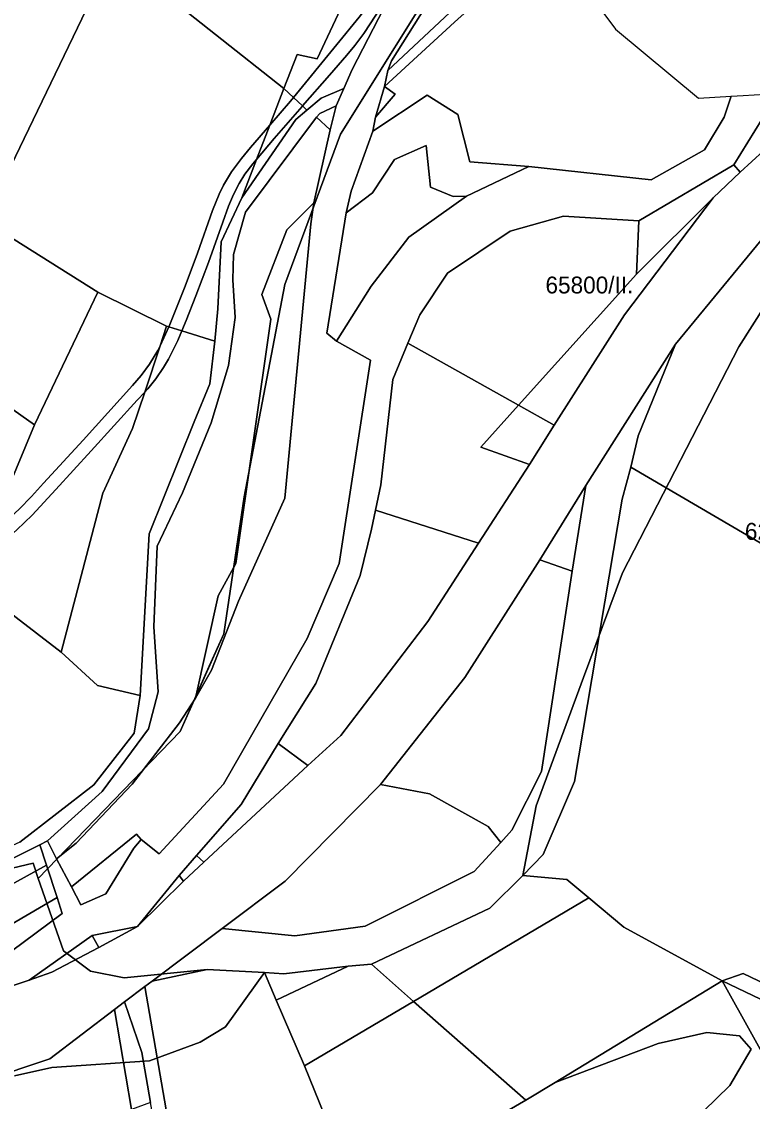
# Model space of a CAD drawing. Extents: x -521261 to -517465, y -1182764 to -1179456.
# Drawn here: x -518451.4 to -518235, y -1181892.1 to -1181572.2 of the extents above; entities that cross this region are included whole.
import ezdxf

# ---------------------------------------------------------------- set-up
doc = ezdxf.new("R2010")
doc.units = 0
for name, color, linetype in [('95610013', 7, 'Continuous'), ('95620013', 7, 'Continuous'), ('95630013', 7, 'Continuous'), ('95640013', 7, 'Continuous'), ('95660013', 7, 'Continuous')]:
    doc.layers.add(name, color=color, linetype=linetype)

msp = doc.modelspace()

# ---------------------------------------------------------------- linework, layer by layer
at = {"layer": '95610013'}
for points in [[(-518476.82, -1181511.94), (-518424.37, -1181552.23), (-518462.54, -1181631.21), (-518499.78, -1181607.82), (-518519.06, -1181596.55), (-518489.59, -1181536.73)], [(-518381.22, -1181518.57), (-518348.05, -1181547.48), (-518360.77, -1181553.84), (-518356.15, -1181566.8), (-518363.84, -1181583.23), (-518369.82, -1181581.93), (-518373.71, -1181591.99), (-518414.21, -1181559.89)], [(-518292.56, -1181544.69), (-518291.45, -1181553.08), (-518275.51, -1181574.4), (-518250.99, -1181594.82), (-518241.23, -1181594.25), (-518243.36, -1181600.52), (-518249.18, -1181610.2), (-518264.94, -1181619.06), (-518301.2, -1181615.05), (-518318.67, -1181613.69), (-518322.27, -1181599.7), (-518331.35, -1181594), (-518347.44, -1181604.6), (-518346.6, -1181600.52), (-518340.75, -1181593.69), (-518343.97, -1181591.39), (-518323.21, -1181572.31)], [(-518414.21, -1181559.89), (-518373.71, -1181591.99), (-518377.91, -1181602.87), (-518383.59, -1181609.43), (-518386.34, -1181612.73), (-518389.22, -1181616.62), (-518391.62, -1181620.62), (-518392.94, -1181623.31), (-518394.86, -1181628.09), (-518399.35, -1181640.79), (-518403.02, -1181650.57), (-518407.53, -1181661.9), (-518407.83, -1181662.59), (-518408.48, -1181662.39), (-518428.88, -1181652.36), (-518462.54, -1181631.21), (-518424.37, -1181552.23)], [(-518519.06, -1181596.55), (-518499.78, -1181607.82), (-518519.82, -1181640.58), (-518447.55, -1181691.59), (-518461.56, -1181724.91), (-518464.37, -1181727.16), (-518465.48, -1181727.97), (-518521.74, -1181659.28), (-518523.32, -1181646.7), (-518529.15, -1181635.61), (-518540.13, -1181623.13), (-518535.82, -1181617.93), (-518521.74, -1181594.76)], [(-518231.23, -1181593.65), (-518226.03, -1181593.35), (-518228.23, -1181607.32), (-518238.63, -1181616.76), (-518240.53, -1181614.63), (-518232.17, -1181601.16)], [(-518364.04, -1181600.44), (-518360.05, -1181604.26), (-518364.91, -1181625.87), (-518372.83, -1181633.83), (-518380.25, -1181653.03), (-518377.62, -1181660.36), (-518387.93, -1181732.71), (-518393.16, -1181742.24), (-518399.93, -1181772.58), (-518404.68, -1181779.92), (-518418.7, -1181798.11), (-518435.27, -1181815.58), (-518441.04, -1181820.23), (-518443.71, -1181814.88), (-518427.58, -1181800.22), (-518413.83, -1181781.65), (-518410.94, -1181770.72), (-518412.23, -1181751.5), (-518411.22, -1181727.56), (-518403.75, -1181711.81), (-518395.27, -1181691.01), (-518390.12, -1181674.09), (-518388.2, -1181659.86), (-518388.81, -1181648.68), (-518388.69, -1181641.14), (-518385.08, -1181628.59)], [(-518210.43, -1181608.65), (-518201.08, -1181598.66), (-518162.04, -1181630.84), (-518143.65, -1181649.33), (-518166.09, -1181691.8), (-518181.28, -1181714.22), (-518201.57, -1181744.52), (-518211.74, -1181738.87), (-518271.03, -1181704.12), (-518268.81, -1181694.86), (-518257.78, -1181667.72), (-518223.62, -1181626.24)], [(-518462.54, -1181631.21), (-518428.88, -1181652.36), (-518447.55, -1181691.59), (-518519.82, -1181640.58), (-518499.78, -1181607.82)], [(-518331.62, -1181608.89), (-518330.32, -1181621.26), (-518323.64, -1181623.98), (-518319.67, -1181623.86), (-518336.69, -1181636.07), (-518347.92, -1181650.56), (-518358.17, -1181666.8), (-518361, -1181664.46), (-518355.26, -1181628.81), (-518347.5, -1181622.93), (-518340.99, -1181613.05)], [(-518382.91, -1181614.3), (-518381.83, -1181613.01), (-518386.22, -1181624.34), (-518392.34, -1181637.45), (-518393.34, -1181657.24), (-518394.18, -1181666.81), (-518403.95, -1181663.79), (-518402.66, -1181660.73), (-518399.81, -1181653.43), (-518396.07, -1181643.56), (-518391.82, -1181631.62), (-518390.11, -1181626.85), (-518388.64, -1181623.36), (-518386.98, -1181620.16), (-518385.28, -1181617.37)], [(-518268.65, -1181631.19), (-518269.27, -1181646.99), (-518304.23, -1181685.78), (-518337.01, -1181667.42), (-518333.51, -1181659), (-518325.31, -1181646.7), (-518306.77, -1181634.23), (-518290.9, -1181629.82)], [(-518408.48, -1181662.39), (-518410.41, -1181668.2), (-518411.08, -1181669.58), (-518413.54, -1181673.62), (-518416, -1181676.99), (-518418.57, -1181679.95), (-518433.23, -1181696.12), (-518444.89, -1181708.88), (-518448.47, -1181712.84), (-518452.15, -1181716.64), (-518455.79, -1181720.01), (-518459.63, -1181723.36), (-518461.56, -1181724.91), (-518447.55, -1181691.59), (-518428.88, -1181652.36)], [(-518407.83, -1181662.59), (-518409.26, -1181665.86), (-518410.41, -1181668.2), (-518408.48, -1181662.39)], [(-518405.17, -1181666.68), (-518403.95, -1181663.79), (-518394.18, -1181666.81), (-518395.65, -1181679.45), (-518400.32, -1181690.69), (-518413.6, -1181723.96), (-518416.35, -1181771.83), (-518428.93, -1181768.84), (-518439.74, -1181758.97), (-518427.4, -1181711.89), (-518418.53, -1181692.71), (-518414.95, -1181681.93), (-518414.04, -1181680.93), (-518411.64, -1181677.96), (-518409.37, -1181674.6), (-518407.95, -1181672.17), (-518406.68, -1181669.78)], [(-518337.01, -1181667.42), (-518304.23, -1181685.78), (-518315.44, -1181698.22), (-518301.03, -1181703.4), (-518316.1, -1181726.67), (-518346.59, -1181716.86), (-518345, -1181709.41), (-518341.51, -1181678.22)], [(-518417.17, -1181684.34), (-518414.95, -1181681.93), (-518418.53, -1181692.71), (-518427.4, -1181711.89), (-518439.74, -1181758.97), (-518460.42, -1181743.1), (-518462.64, -1181741.12), (-518466.51, -1181737.53), (-518464.59, -1181732.37), (-518461.48, -1181730.07), (-518458.77, -1181727.94), (-518456.47, -1181725.99), (-518452.81, -1181722.77), (-518448.24, -1181718.36), (-518441.26, -1181710.8), (-518430.81, -1181699.37)], [(-518273.51, -1181713.67), (-518271.03, -1181704.12), (-518211.74, -1181738.87), (-518201.57, -1181744.52), (-518174.5, -1181758.25), (-518185.6, -1181810.01), (-518196.73, -1181867.61), (-518217.29, -1181863.99), (-518237.7, -1181854.2), (-518243.96, -1181856.31), (-518273.09, -1181840.42), (-518283.47, -1181831.75), (-518289.97, -1181826.31), (-518302.96, -1181825.14), (-518296.94, -1181818.88), (-518287.7, -1181797.29)], [(-518346.59, -1181716.86), (-518316.1, -1181726.67), (-518331.13, -1181749.88), (-518356.9, -1181783.65), (-518366.69, -1181792.51), (-518375.39, -1181786.06), (-518364.24, -1181768.26), (-518351.11, -1181736.23), (-518347.8, -1181722.52)], [(-518460.42, -1181743.1), (-518439.74, -1181758.97), (-518428.93, -1181768.84), (-518416.35, -1181771.83), (-518418.1, -1181782.97), (-518430.01, -1181798.28), (-518451.98, -1181815.29), (-518465.35, -1181821.3), (-518479.21, -1181819.93), (-518486.56, -1181817.64), (-518501.45, -1181807.02), (-518529.59, -1181794.49), (-518566.25, -1181771.18), (-518553.91, -1181776.63), (-518531.62, -1181780.05), (-518502.35, -1181773.42), (-518481.38, -1181762.2)], [(-518404.75, -1181825.16), (-518403.42, -1181826.84), (-518417.05, -1181840.21)], [(-518417.05, -1181840.21), (-518428.59, -1181846.46), (-518430.51, -1181842.88)], [(-518396.5, -1181852.96), (-518379.46, -1181853.84), (-518376.06, -1181862.1), (-518367.68, -1181881.56), (-518357.49, -1181906.63), (-518350.22, -1181919.64), (-518342.33, -1181934.69), (-518357.25, -1181947.67), (-518394.95, -1181973.55), (-518397.34, -1181959.64), (-518414.92, -1181857.99), (-518412.79, -1181856.47)], [(-518373.71, -1181854.29), (-518354.74, -1181851.96), (-518376.06, -1181862.1), (-518379.46, -1181853.84)], [(-518354.74, -1181851.96), (-518347.83, -1181851.39), (-518335.33, -1181862.43), (-518367.68, -1181881.56), (-518376.06, -1181862.1)], [(-518367.68, -1181881.56), (-518335.33, -1181862.43), (-518302.11, -1181891.7), (-518350.22, -1181919.64), (-518357.49, -1181906.63)], [(-518443.06, -1181879.44), (-518423.93, -1181864.88), (-518418.91, -1181894.43), (-518563.19, -1181948.17), (-518569.57, -1181929.4), (-518533.23, -1181906.38), (-518501.17, -1181898.93)], [(-518238.76, -1181872.67), (-518235.39, -1181876.59), (-518241.66, -1181887.31), (-518292.42, -1181936.84), (-518324.52, -1181960.18), (-518326.35, -1181957.27), (-518342.33, -1181934.69), (-518350.22, -1181919.64), (-518302.11, -1181891.7), (-518293.39, -1181886.48), (-518262.89, -1181874.89), (-518248.46, -1181871.63)]]:
    msp.add_lwpolyline(points, close=True, dxfattribs=at)
msp.add_lwpolyline([(-518463.58, -1181824.77), (-518446.06, -1181816.02), (-518444.06, -1181822.06), (-518462.21, -1181832.05)], dxfattribs=at)
at = {"layer": '95620013'}
for points in [[(-518174.5, -1181758.25), (-518176.04, -1181791.27), (-518184.18, -1181816.88), (-518186.5, -1181837.96), (-518187.07, -1181860.77), (-518193.46, -1181875.24), (-518206.25, -1181872.88), (-518216.74, -1181869.34), (-518243.96, -1181856.31), (-518237.7, -1181854.2), (-518217.29, -1181863.99), (-518196.73, -1181867.61), (-518185.6, -1181810.01)], [(-518302.96, -1181825.14), (-518289.97, -1181826.31), (-518283.47, -1181831.75), (-518335.33, -1181862.43), (-518347.83, -1181851.39), (-518312.78, -1181834.79)], [(-518283.47, -1181831.75), (-518273.09, -1181840.42), (-518243.96, -1181856.31), (-518293.39, -1181886.48), (-518302.11, -1181891.7), (-518335.33, -1181862.43)], [(-518243.96, -1181856.31), (-518216.74, -1181869.34), (-518206.25, -1181872.88), (-518193.46, -1181875.24), (-518210.07, -1181898.25), (-518234.59, -1181915.51), (-518260.74, -1181923.8), (-518297.47, -1181944.62), (-518324.52, -1181960.18), (-518292.42, -1181936.84), (-518241.77, -1181903.92), (-518224.92, -1181890.6)], [(-518238.76, -1181872.67), (-518248.46, -1181871.63), (-518262.89, -1181874.89), (-518293.39, -1181886.48), (-518243.96, -1181856.31), (-518224.92, -1181890.6), (-518241.77, -1181903.92), (-518292.42, -1181936.84), (-518241.66, -1181887.31), (-518235.39, -1181876.59)]]:
    msp.add_lwpolyline(points, close=True, dxfattribs=at)
at = {"layer": '95630013'}
for points in [[(-518292.99, -1181541.03), (-518292.56, -1181544.69), (-518323.21, -1181572.31), (-518343.97, -1181591.39), (-518343, -1181586.61), (-518304.74, -1181550.83)], [(-518284.29, -1181709.64), (-518288.33, -1181734.98), (-518297.97, -1181731.65)], [(-518297.97, -1181731.65), (-518288.33, -1181734.98), (-518297.49, -1181794.35), (-518306.21, -1181811.72), (-518309.53, -1181815.34), (-518313.24, -1181810.57), (-518330.63, -1181800.91), (-518345.1, -1181798.17), (-518320.12, -1181766.51)], [(-518345.1, -1181798.17), (-518330.63, -1181800.91), (-518313.24, -1181810.57), (-518309.53, -1181815.34), (-518317.42, -1181823.95), (-518349.68, -1181840.18), (-518370.51, -1181842.96), (-518392.04, -1181840.87), (-518373.39, -1181826.78)]]:
    msp.add_lwpolyline(points, close=True, dxfattribs=at)
for points in [[(-518451.98, -1181815.29), (-518430.01, -1181798.28), (-518418.1, -1181782.97), (-518416.35, -1181771.83), (-518413.6, -1181723.96), (-518400.32, -1181690.69), (-518395.65, -1181679.45), (-518394.18, -1181666.81), (-518393.34, -1181657.24), (-518392.34, -1181637.45), (-518386.22, -1181624.34), (-518370.22, -1181601.17), (-518366.91, -1181598.39), (-518362.67, -1181594.83), (-518355.96, -1181592.03), (-518358.22, -1181597.08), (-518363.05, -1181599.36), (-518364.04, -1181600.44), (-518385.08, -1181628.59), (-518388.69, -1181641.14), (-518388.81, -1181648.68), (-518388.2, -1181659.86), (-518390.12, -1181674.09), (-518395.27, -1181691.01), (-518403.75, -1181711.81), (-518411.22, -1181727.56), (-518412.23, -1181751.5), (-518410.94, -1181770.72), (-518413.83, -1181781.65), (-518427.58, -1181800.22), (-518443.71, -1181814.88), (-518446.06, -1181816.02), (-518463.58, -1181824.77)], [(-518462.19, -1181853.28), (-518439.36, -1181836.36), (-518440.9, -1181831.61), (-518444.06, -1181822.06), (-518446.06, -1181816.02), (-518443.71, -1181814.88), (-518441.04, -1181820.23), (-518436.68, -1181828.52), (-518433.85, -1181833.87), (-518426.44, -1181830.61), (-518418.2, -1181817.08), (-518415.97, -1181814.43), (-518410.71, -1181818.75), (-518391.63, -1181798.11), (-518366.86, -1181754.89), (-518357.33, -1181732.66), (-518348.13, -1181672.51), (-518358.17, -1181666.8), (-518347.92, -1181650.56), (-518336.69, -1181636.07), (-518319.67, -1181623.86), (-518301.2, -1181615.05), (-518264.94, -1181619.06), (-518249.18, -1181610.2), (-518243.36, -1181600.52), (-518241.23, -1181594.25), (-518237.69, -1181594.04), (-518231.23, -1181593.65)], [(-518232.17, -1181601.16), (-518240.53, -1181614.63), (-518268.65, -1181631.19), (-518290.9, -1181629.82), (-518306.77, -1181634.23), (-518325.31, -1181646.7), (-518333.51, -1181659), (-518337.01, -1181667.42), (-518341.51, -1181678.22), (-518345, -1181709.41), (-518346.59, -1181716.86), (-518347.8, -1181722.52), (-518351.11, -1181736.23), (-518364.24, -1181768.26), (-518375.39, -1181786.06), (-518386.42, -1181804.08), (-518399.59, -1181819.23), (-518404.75, -1181825.16), (-518417.05, -1181840.21), (-518430.51, -1181842.88), (-518449.2, -1181856.15), (-518511.46, -1181876.67)]]:
    msp.add_lwpolyline(points, dxfattribs=at)
at = {"layer": '95640013'}
for points in [[(-518292.92, -1181519.25), (-518288.8, -1181522.19), (-518294.6, -1181527.65), (-518292.99, -1181541.03), (-518304.74, -1181550.83), (-518343, -1181586.61), (-518341.85, -1181583.76), (-518330.14, -1181565.02)], [(-518348.05, -1181547.48), (-518340.67, -1181554.63), (-518345.13, -1181561.85), (-518348.85, -1181567.48), (-518351.43, -1181570.85), (-518358.03, -1181578.9), (-518370.88, -1181594.65), (-518373.71, -1181591.99), (-518369.82, -1181581.93), (-518363.84, -1181583.23), (-518356.15, -1181566.8), (-518360.77, -1181553.84)], [(-518340.67, -1181554.63), (-518338.07, -1181557.14), (-518338.36, -1181557.58), (-518346.55, -1181570.23), (-518350.1, -1181575.69), (-518352.7, -1181579.27), (-518355.05, -1181582.12), (-518360.25, -1181588.07), (-518368.24, -1181597.13), (-518370.88, -1181594.65), (-518358.03, -1181578.9), (-518351.43, -1181570.85), (-518348.85, -1181567.48), (-518345.13, -1181561.85)], [(-518338.36, -1181557.58), (-518338.07, -1181557.14), (-518337.29, -1181557.9), (-518342.54, -1181565.05), (-518353.55, -1181586.4), (-518355.96, -1181592.03), (-518362.67, -1181594.83), (-518366.91, -1181598.39), (-518368.24, -1181597.13), (-518360.25, -1181588.07), (-518355.05, -1181582.12), (-518352.7, -1181579.27), (-518350.1, -1181575.69), (-518346.55, -1181570.23)], [(-518373.71, -1181591.99), (-518370.88, -1181594.65), (-518371.79, -1181595.78), (-518377.91, -1181602.87)], [(-518343.97, -1181591.39), (-518340.75, -1181593.69), (-518346.6, -1181600.52)], [(-518370.88, -1181594.65), (-518368.24, -1181597.13), (-518368.36, -1181597.27), (-518376.62, -1181606.83), (-518381.83, -1181613.01), (-518377.91, -1181602.87), (-518371.79, -1181595.78)], [(-518322.27, -1181599.7), (-518318.67, -1181613.69), (-518301.2, -1181615.05), (-518319.67, -1181623.86), (-518323.64, -1181623.98), (-518330.32, -1181621.26), (-518331.62, -1181608.89), (-518340.99, -1181613.05), (-518347.5, -1181622.93), (-518355.26, -1181628.81), (-518353.86, -1181622.4), (-518347.44, -1181604.6), (-518331.35, -1181594)], [(-518368.36, -1181597.27), (-518368.24, -1181597.13), (-518366.91, -1181598.39), (-518370.22, -1181601.17), (-518386.22, -1181624.34), (-518381.83, -1181613.01), (-518376.62, -1181606.83)], [(-518358.22, -1181597.08), (-518360.05, -1181604.26), (-518364.04, -1181600.44), (-518363.05, -1181599.36)], [(-518377.91, -1181602.87), (-518381.83, -1181613.01), (-518382.91, -1181614.3), (-518385.28, -1181617.37), (-518386.98, -1181620.16), (-518388.64, -1181623.36), (-518390.11, -1181626.85), (-518391.82, -1181631.62), (-518396.07, -1181643.56), (-518399.81, -1181653.43), (-518402.66, -1181660.73), (-518403.95, -1181663.79), (-518407.83, -1181662.59), (-518407.53, -1181661.9), (-518403.02, -1181650.57), (-518399.35, -1181640.79), (-518394.86, -1181628.09), (-518392.94, -1181623.31), (-518391.62, -1181620.62), (-518389.22, -1181616.62), (-518386.34, -1181612.73), (-518383.59, -1181609.43)], [(-518240.53, -1181614.63), (-518238.63, -1181616.76), (-518246.56, -1181624.36), (-518269.27, -1181646.99), (-518268.65, -1181631.19)], [(-518364.91, -1181625.87), (-518365.73, -1181632.04), (-518373.41, -1181713.36), (-518387.15, -1181743.87), (-518395.15, -1181764.35), (-518399.93, -1181772.58), (-518393.16, -1181742.24), (-518387.93, -1181732.71), (-518377.62, -1181660.36), (-518380.25, -1181653.03), (-518372.83, -1181633.83)], [(-518269.27, -1181646.99), (-518246.56, -1181624.36), (-518272.91, -1181659.04), (-518293.66, -1181691.71), (-518304.23, -1181685.78)], [(-518407.83, -1181662.59), (-518403.95, -1181663.79), (-518405.17, -1181666.68), (-518406.68, -1181669.78), (-518407.95, -1181672.17), (-518409.37, -1181674.6), (-518411.64, -1181677.96), (-518414.04, -1181680.93), (-518414.95, -1181681.93), (-518410.41, -1181668.2), (-518409.26, -1181665.86)], [(-518410.41, -1181668.2), (-518414.95, -1181681.93), (-518417.17, -1181684.34), (-518430.81, -1181699.37), (-518441.26, -1181710.8), (-518448.24, -1181718.36), (-518452.81, -1181722.77), (-518456.47, -1181725.99), (-518458.77, -1181727.94), (-518461.48, -1181730.07), (-518464.59, -1181732.37), (-518463.74, -1181730.1), (-518461.56, -1181724.91), (-518459.63, -1181723.36), (-518455.79, -1181720.01), (-518452.15, -1181716.64), (-518448.47, -1181712.84), (-518444.89, -1181708.88), (-518433.23, -1181696.12), (-518418.57, -1181679.95), (-518416, -1181676.99), (-518413.54, -1181673.62), (-518411.08, -1181669.58)], [(-518268.81, -1181694.86), (-518271.03, -1181704.12), (-518273.51, -1181713.67), (-518287.7, -1181797.29), (-518296.94, -1181818.88), (-518302.96, -1181825.14), (-518312.78, -1181834.79), (-518347.83, -1181851.39), (-518354.74, -1181851.96), (-518373.71, -1181854.29), (-518379.46, -1181853.84), (-518396.5, -1181852.96), (-518412.79, -1181856.47), (-518392.04, -1181840.87), (-518370.51, -1181842.96), (-518349.68, -1181840.18), (-518317.42, -1181823.95), (-518309.53, -1181815.34), (-518306.21, -1181811.72), (-518297.49, -1181794.35), (-518288.33, -1181734.98), (-518284.29, -1181709.64), (-518257.78, -1181667.72)], [(-518304.23, -1181685.78), (-518293.66, -1181691.71), (-518298.38, -1181699.15), (-518301.03, -1181703.4), (-518315.44, -1181698.22)], [(-518375.39, -1181786.06), (-518366.69, -1181792.51), (-518397.42, -1181821.23), (-518399.59, -1181819.23), (-518386.42, -1181804.08)], [(-518415.97, -1181814.43), (-518418.2, -1181817.08), (-518426.44, -1181830.61), (-518433.85, -1181833.87), (-518436.68, -1181828.52), (-518417.35, -1181812.86)], [(-518397.42, -1181821.23), (-518403.42, -1181826.84), (-518404.75, -1181825.16), (-518399.59, -1181819.23)], [(-518440.9, -1181831.61), (-518439.36, -1181836.36), (-518462.19, -1181853.28), (-518493.06, -1181867.9), (-518531.13, -1181867.61), (-518550.76, -1181876.48), (-518584.29, -1181866.38), (-518588.11, -1181867.31), (-518597.74, -1181856.58), (-518562.08, -1181864.17), (-518526.41, -1181862.85), (-518492.11, -1181855.83), (-518458.32, -1181841.87)], [(-518430.51, -1181842.88), (-518428.59, -1181846.46), (-518442.42, -1181853.8), (-518449.2, -1181856.15)], [(-518420.92, -1181862.58), (-518414.92, -1181857.99), (-518397.34, -1181959.64), (-518406.88, -1181927.15), (-518413.21, -1181892.42), (-518415.81, -1181877.57)], [(-518423.93, -1181864.88), (-518420.92, -1181862.58), (-518415.81, -1181877.57), (-518413.21, -1181892.42), (-518418.91, -1181894.43)]]:
    msp.add_lwpolyline(points, close=True, dxfattribs=at)
for points in [[(-518330.14, -1181565.02), (-518341.85, -1181583.76), (-518343, -1181586.61), (-518343.97, -1181591.39), (-518346.6, -1181600.52), (-518347.44, -1181604.6), (-518353.86, -1181622.4), (-518355.26, -1181628.81), (-518361, -1181664.46), (-518358.17, -1181666.8), (-518348.13, -1181672.51), (-518357.33, -1181732.66), (-518366.86, -1181754.89), (-518391.63, -1181798.11), (-518410.71, -1181818.75), (-518415.97, -1181814.43), (-518417.35, -1181812.86), (-518436.68, -1181828.52), (-518441.04, -1181820.23), (-518435.27, -1181815.58), (-518418.7, -1181798.11), (-518404.68, -1181779.92), (-518399.93, -1181772.58), (-518395.15, -1181764.35), (-518387.15, -1181743.87), (-518373.41, -1181713.36), (-518365.73, -1181632.04), (-518364.91, -1181625.87), (-518360.05, -1181604.26), (-518358.22, -1181597.08), (-518355.96, -1181592.03), (-518353.55, -1181586.4), (-518342.54, -1181565.05)], [(-518511.46, -1181876.67), (-518449.2, -1181856.15), (-518442.42, -1181853.8), (-518428.59, -1181846.46), (-518417.05, -1181840.21), (-518403.42, -1181826.84), (-518397.42, -1181821.23), (-518366.69, -1181792.51), (-518356.9, -1181783.65), (-518331.13, -1181749.88), (-518316.1, -1181726.67), (-518301.03, -1181703.4), (-518298.38, -1181699.15), (-518293.66, -1181691.71), (-518272.91, -1181659.04), (-518246.56, -1181624.36), (-518238.63, -1181616.76), (-518228.23, -1181607.32)], [(-518223.62, -1181626.24), (-518257.78, -1181667.72), (-518284.29, -1181709.64), (-518297.97, -1181731.65), (-518320.12, -1181766.51), (-518345.1, -1181798.17), (-518373.39, -1181826.78), (-518392.04, -1181840.87), (-518412.79, -1181856.47), (-518414.92, -1181857.99), (-518420.92, -1181862.58), (-518423.93, -1181864.88), (-518443.06, -1181879.44), (-518501.17, -1181898.93), (-518533.23, -1181906.38), (-518560.65, -1181908.71), (-518594.09, -1181908.98), (-518616.77, -1181907.64), (-518653.59, -1181905.09), (-518704.59, -1181895.96), (-518740.3, -1181896.33), (-518841.96, -1181963.21)], [(-518462.21, -1181832.05), (-518444.06, -1181822.06), (-518440.9, -1181831.61), (-518458.32, -1181841.87)]]:
    msp.add_lwpolyline(points, dxfattribs=at)
at = {"layer": '95660013'}
for points in [[(-518292, -1181501.5), (-518357, -1181605.5), (-518373.5, -1181650), (-518385.5, -1181713), (-518391.5, -1181753.5), (-518404.5, -1181782.5), (-518446.5, -1181826), (-518448, -1181821.5), (-518463, -1181825), (-518477, -1181825), (-518506, -1181816), (-518572, -1181787), (-518554.5, -1181761), (-518541, -1181732.5), (-518535.5, -1181702.5), (-518541, -1181680), (-518568, -1181628), (-518591, -1181563)], [(-518222.5, -1181642.5), (-518239, -1181668.5), (-518273.5, -1181735.5), (-518285, -1181766.5), (-518299, -1181804.5), (-518302.96, -1181825.14), (-518312.78, -1181834.79), (-518347.83, -1181851.39), (-518354.74, -1181851.96), (-518373.71, -1181854.29), (-518379.46, -1181853.84), (-518396.5, -1181852.96), (-518421, -1181855.5), (-518431, -1181853.5), (-518439, -1181847.5), (-518446.5, -1181826), (-518404.5, -1181782.5), (-518395.82, -1181763.13), (-518391.5, -1181753.5), (-518385.5, -1181713), (-518373.5, -1181650), (-518357, -1181605.5), (-518292, -1181501.5)], [(-518232.93, -1181508.15), (-518243.76, -1181510.04), (-518252.51, -1181510.92), (-518279.66, -1181513.62), (-518288.8, -1181522.19), (-518294.6, -1181527.65), (-518292.99, -1181541.03), (-518292.56, -1181544.69), (-518291.45, -1181553.08), (-518275.51, -1181574.4), (-518250.99, -1181594.82), (-518241.23, -1181594.25), (-518237.69, -1181594.04), (-518231.23, -1181593.65)], [(-518217.29, -1181863.99), (-518237.7, -1181854.2), (-518243.96, -1181856.31), (-518273.09, -1181840.42), (-518283.47, -1181831.75), (-518289.97, -1181826.31), (-518302.96, -1181825.14), (-518299, -1181804.5), (-518285, -1181766.5), (-518273.5, -1181735.5), (-518239, -1181668.5), (-518222.5, -1181642.5)], [(-518463, -1181825), (-518448, -1181821.5), (-518446.5, -1181826), (-518439, -1181847.5), (-518431, -1181853.5), (-518421, -1181855.5), (-518396.5, -1181852.96), (-518379.46, -1181853.84), (-518391, -1181870), (-518398.5, -1181874.5), (-518413.5, -1181880), (-518442.5, -1181882), (-518453.5, -1181884.5)], [(-518292.42, -1181936.84), (-518241.66, -1181887.31), (-518235.39, -1181876.59), (-518238.76, -1181872.67), (-518248.46, -1181871.63), (-518262.89, -1181874.89), (-518293.39, -1181886.48), (-518302.11, -1181891.7), (-518335.33, -1181862.43), (-518347.83, -1181851.39), (-518312.78, -1181834.79), (-518302.96, -1181825.14), (-518289.97, -1181826.31), (-518283.47, -1181831.75), (-518273.09, -1181840.42), (-518243.96, -1181856.31), (-518237.7, -1181854.2), (-518217.29, -1181863.99)], [(-518453.5, -1181884.5), (-518442.5, -1181882), (-518413.5, -1181880), (-518398.5, -1181874.5), (-518391, -1181870), (-518379.46, -1181853.84), (-518373.71, -1181854.29), (-518354.74, -1181851.96), (-518347.83, -1181851.39), (-518335.33, -1181862.43), (-518302.11, -1181891.7), (-518293.39, -1181886.48), (-518262.89, -1181874.89), (-518248.46, -1181871.63), (-518238.76, -1181872.67), (-518235.39, -1181876.59), (-518241.66, -1181887.31), (-518292.42, -1181936.84)]]:
    msp.add_lwpolyline(points, dxfattribs=at)

# ---------------------------------------------------------------- texts
for s, rotation, p in [('65800/II.', 0, (-518296.27, -1181652.7)), ('62441/III.', 360, (-518237.2, -1181725.68))]:
    msp.add_text(s, height=5, rotation=rotation, dxfattribs=at).set_placement(p)

doc.saveas('drawing.dxf')
